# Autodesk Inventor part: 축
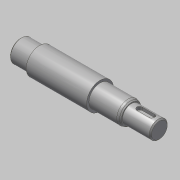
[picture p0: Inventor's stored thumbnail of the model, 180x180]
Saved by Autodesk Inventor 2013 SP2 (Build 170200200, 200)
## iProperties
Created: 2016-06
Part Number: 축
Material: 강철, 연강
Document SubType Name: Modeling
Designer: mduedu
Density: 7.86 g/cm^3
Author: mduedu
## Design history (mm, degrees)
sketch "스케치1"
  geometry: L1 (-62, 0)-(62, 0); L2 (-62, 0)-(-62, 10); L3 (-62, 10)-(-45, 10); L4 (-45, 10)-(-45, 12); L5 (-45, 12)-(9, 12); L6 (9, 12)-(9, 10); L7 (9, 10)-(37, 10); L8 (37, 10)-(37, 8); L9 (37, 8)-(62, 8); L10 (62, 8)-(62, 0); 2 further points
  constraints: 20 end point, 5 parallel, 2 perpendicular, 1 coincident, 1 collinear, 1 horizontal, 1 midpoint, 1 vertical
  dimensions: "d0" = 124 distance of L1.start L1.end; "d2" = 16 diameter of L9 L1; "d3" = 20 diameter of L7 L1; "d4" = 24 diameter of L5 L1; "d5" = 20 diameter of L3 L1; "d6" = 17 distance of L2.end L3.end; "d7" = 25 distance of L8.end L9.end; "d8" = 53 distance from line of L5.end L10
revolve "회전1" sketch "스케치1" stored, may be unused: angle "d9" = 90 deg
chamfer "모따기1" distance "d10" = 2; stored, may be unused: second distance "d11" = 2, angle "d12" = 30 deg
fillet "모깎기1" dims "d13" = 4
node "작업 평면1"
sketch "스케치2"
  geometry: L1 (-5, 2.5)-(6, 2.5); L2 (6, -2.5)-(-5, -2.5); L3 (-5, 0)-(6, 0); L4 (-12.5, 8.845)-(-12.5, -8.845) reference; A1 r 2.5 centre (-5, 0) between (-5, 2.5) and (-5, -2.5); A2 r 2.5 centre (6, 0) between (6, -2.5) and (6, 2.5); 1 further point
  constraints: 6 end point, 4 point on circle, 3 tangent, 2 centre point, 2 parallel, 1 horizontal, 1 horizontal alignment
  dimensions: "d14" = 5 distance edge to line of A1 L4; "d15" = 5 distance between parallel lines of L2 L1; "d16" = 16 dimension on A2 A1
extrude "돌출1" cut sketch "스케치2" distance "d17" = 3; taper "d18" = 0 deg
chamfer "모따기2" distance "d19" = 1; stored, may be unused: second distance "d20" = 2, angle "d21" = 30 deg
sketch "스케치3"
  geometry: L1 (-37, -8)-(-61, -8) reference; L2 (-62, -7)-(-62, 7) reference; L3 (-38.5, -8)-(-40, -6.5); L4 (-40, -6.5)-(-40, -8); L5 (-38.5, -8)-(-40, -8); 1 further point
  constraints: 6 end point, 2 point on line, 1 collinear, 1 vertical
  dimensions: "d22" = 45 deg angle of L4 L3; "d23" = 22 distance between parallel lines of L2 L4; "d24" = 3 diameter of L3.start L4
revolve "회전2" stored, may be unused: angle "d25" = 90 deg
node "작업점1"
sketch "스케치4"
  geometry: 1 further point
hole "구멍1" sketch "스케치4" at (0, 0) diameter "d26" = 3.242; stored, may be unused: countersink angle "d30" = 90 deg, drill point angle "d32" = 120 deg; dims "d27" = 8, "d28" = 4, "d29" = 2, "d31" = 11
chamfer "모따기3" distance "d33" = 2; stored, may be unused: second distance "d34" = 2, angle "d35" = 30 deg
node "솔리드1"
